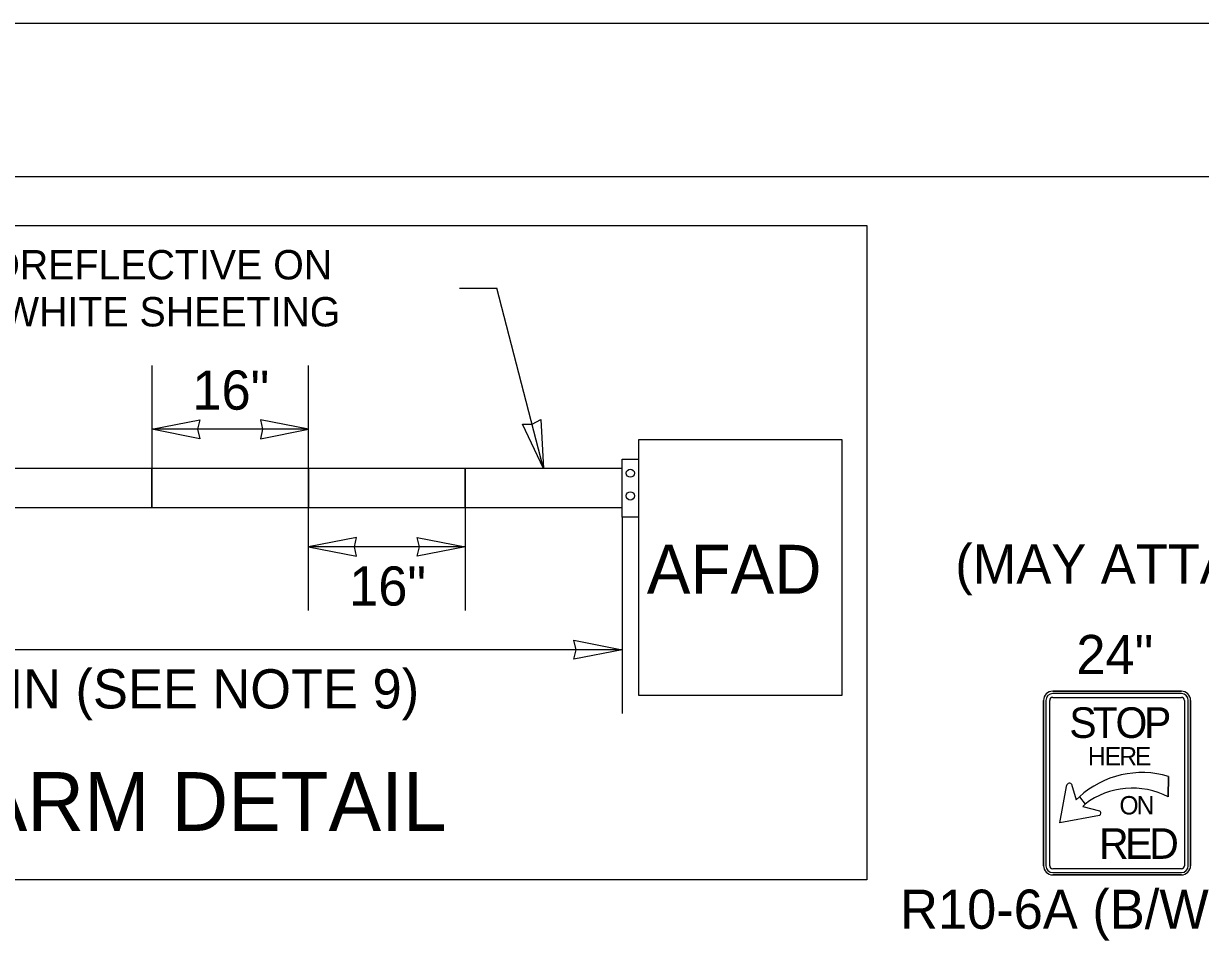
# Model space of a CAD drawing. Extents: x 99999.1 to 100095.7, y 99995 to 100010.7.
# Drawn here: x 100049.243 to 100051.645, y 100008.807 to 100010.687 of the extents above; entities that cross this region are included whole.
import ezdxf

# ---------------------------------------------------------------- set-up
doc = ezdxf.new("R2010")
doc.units = 0
for name, color, linetype in [('SH_GI_PlotLimits', 7, 'Continuous'), ('SH_GI_SheetBorder', 7, 'Continuous'), ('TR_SN_ConstructionSigns', 7, 'Continuous'), ('TR_WZ_WorkZoneDetails', 7, 'Continuous')]:
    doc.layers.add(name, color=color, linetype=linetype)

msp = doc.modelspace()

# ---------------------------------------------------------------- linework, layer by layer
at = {"layer": 'SH_GI_PlotLimits'}
msp.add_lwpolyline([(100039.0625, 99999.6875), (100056.0625, 99999.6875), (100056.0625, 100010.6875), (100039.0625, 100010.6875)], close=True, dxfattribs=at)
at = {"layer": 'SH_GI_SheetBorder'}
msp.add_line((100040, 100010.375), (100055.75, 100010.375), dxfattribs=at)
at = {"layer": 'TR_SN_ConstructionSigns'}
for p, q in [((100051.6061, 100009.3241), (100051.3436, 100009.3241)), ((100051.3436, 100009.3241), (100051.6061, 100009.3241)), ((100051.6061, 100009.3241), (100051.3436, 100009.3241)), ((100051.3436, 100009.3241), (100051.6061, 100009.3241)), ((100051.6061, 100009.3194), (100051.3436, 100009.3194)), ((100051.3436, 100009.3116), (100051.6061, 100009.3116)), ((100051.3249, 100009.3054), (100051.3249, 100008.9679)), ((100051.3249, 100008.9679), (100051.3249, 100009.3054)), ((100051.3249, 100009.3054), (100051.3249, 100008.9679)), ((100051.3249, 100008.9679), (100051.3249, 100009.3054)), ((100051.3296, 100009.3054), (100051.3296, 100008.9679)), ((100051.3374, 100008.9679), (100051.3374, 100009.3054)), ((100051.6124, 100009.3054), (100051.6124, 100008.9679)), ((100051.6202, 100008.9679), (100051.6202, 100009.3054)), ((100051.6249, 100008.9679), (100051.6249, 100009.3054)), ((100051.6249, 100009.3054), (100051.6249, 100008.9679)), ((100051.6249, 100008.9679), (100051.6249, 100009.3054)), ((100051.6249, 100009.3054), (100051.6249, 100008.9679)), ((100051.5798, 100009.1503), (100051.5795, 100009.1084)), ((100051.5795, 100009.1084), (100051.5798, 100009.1503)), ((100051.3577, 100009.0554), (100051.3713, 100009.1298)), ((100051.3821, 100009.1346), (100051.3915, 100009.1022)), ((100051.3915, 100009.1022), (100051.3979, 100009.1086)), ((100051.3979, 100009.1086), (100051.4095, 100009.0937)), ((100051.3979, 100009.1086), (100051.4095, 100009.0937)), ((100051.4095, 100009.0937), (100051.4048, 100009.0889)), ((100051.4048, 100009.0889), (100051.439, 100009.0797)), ((100051.4388, 100009.0704), (100051.3577, 100009.0554)), ((100051.6061, 100008.9616), (100051.3436, 100008.9616)), ((100051.3436, 100008.9538), (100051.6061, 100008.9538)), ((100051.3436, 100008.9491), (100051.6061, 100008.9491)), ((100051.6061, 100008.9491), (100051.3436, 100008.9491)), ((100051.3436, 100008.9491), (100051.6061, 100008.9491)), ((100051.6061, 100008.9491), (100051.3436, 100008.9491))]:
    msp.add_line(p, q, dxfattribs=at)
for centre, radius, start, end in [((100051.3436, 100009.3054), 0.0187, 90, 180), ((100051.3436, 100009.3054), 0.0187, 90, 180), ((100051.3436, 100009.3054), 0.0187, 90, 180), ((100051.3436, 100009.3054), 0.0187, 90, 180), ((100051.3436, 100009.3054), 0.0141, 90, 180), ((100051.3436, 100009.3054), 0.00625, 90, 180), ((100051.6061, 100009.3054), 0.0187, 0, 90), ((100051.6061, 100009.3054), 0.0187, 0, 90), ((100051.6061, 100009.3054), 0.0187, 0, 90), ((100051.6061, 100009.3054), 0.0187, 0, 90), ((100051.6061, 100009.3054), 0.0141, 0, 90), ((100051.6061, 100009.3054), 0.00625, 0, 90), ((100051.5261, 100008.9672), 0.1909, 73.6434, 132.2131), ((100051.5261, 100008.9672), 0.1909, 73.6434, 132.2131), ((100051.506, 100008.9678), 0.1586, 62.4149, 127.4769), ((100051.506, 100008.9678), 0.1586, 62.4149, 127.4769), ((100051.3436, 100008.9679), 0.0187, 180, 270), ((100051.3436, 100008.9679), 0.0187, 180, 270), ((100051.3436, 100008.9679), 0.0187, 180, 270), ((100051.3436, 100008.9679), 0.0187, 180, 270), ((100051.3436, 100008.9679), 0.0141, 180, 270), ((100051.3436, 100008.9679), 0.00625, 180, 270), ((100051.6061, 100008.9679), 0.0187, 270, 0), ((100051.6061, 100008.9679), 0.0187, 270, 0), ((100051.6061, 100008.9679), 0.0187, 270, 0), ((100051.6061, 100008.9679), 0.0141, 270, 0), ((100051.6061, 100008.9679), 0.00625, 270, 0), ((100051.6061, 100008.9679), 0.0187, 270, 0)]:
    msp.add_arc(centre, radius, start, end, dxfattribs=at)
for centre, major_axis, ratio, start_param, end_param in [((100051.3777, 100009.1299), (-0.00647, -0.00009), 0.989437, 3.962549, 6.283185), ((100051.4366, 100009.0751), (-0.0046, 0.00239), 0.999053, 2.490568, 4.712389)]:
    msp.add_ellipse(centre, major_axis=major_axis, ratio=ratio, start_param=start_param, end_param=end_param, dxfattribs=at)
at = {"layer": 'TR_WZ_WorkZoneDetails'}
for p, q in [((100050.1326, 100010.147), (100050.2088, 100010.147)), ((100050.3043, 100009.779), (100050.2088, 100010.147)), ((100049.5043, 100009.989), (100049.5043, 100009.779)), ((100049.8243, 100009.779), (100049.8243, 100009.989)), ((100049.8243, 100009.859), (100049.5043, 100009.859)), ((100049.8243, 100009.489), (100049.8243, 100009.699)), ((100050.1443, 100009.699), (100050.1443, 100009.489)), ((100050.4643, 100009.6797), (100050.4643, 100009.279)), ((100050.1443, 100009.619), (100049.8243, 100009.619)), ((100050.4643, 100009.409), (100048.6643, 100009.409))]:
    msp.add_line(p, q, dxfattribs=at)
for points in [[(100047.6374, 100010.275), (100050.9639, 100010.275), (100050.9639, 100008.939), (100047.6374, 100008.939)], [(100049.5043, 100009.859), (100049.6026, 100009.8783), (100049.5981, 100009.859), (100049.6026, 100009.8397)], [(100049.8243, 100009.859), (100049.7261, 100009.8783), (100049.7306, 100009.859), (100049.7261, 100009.8397)], [(100050.3043, 100009.779), (100050.2611, 100009.8693), (100050.2809, 100009.8697), (100050.2984, 100009.879)], [(100050.4643, 100009.7983), (100050.4977, 100009.7983), (100050.4977, 100009.6797), (100050.4643, 100009.6797)], [(100049.8243, 100009.619), (100049.9226, 100009.5997), (100049.9181, 100009.619), (100049.9226, 100009.6383)], [(100050.1443, 100009.619), (100050.0461, 100009.5997), (100050.0506, 100009.619), (100050.0461, 100009.6383)], [(100050.4643, 100009.409), (100050.3661, 100009.3897), (100050.3706, 100009.409), (100050.3661, 100009.4283)]]:
    msp.add_lwpolyline(points, close=True, dxfattribs=at)
for points in [[(100050.4977, 100009.6797), (100050.4977, 100009.3163), (100050.9139, 100009.3163), (100050.9139, 100009.8374), (100050.4977, 100009.8374), (100050.4977, 100009.7983), (100050.4977, 100009.6797)], [(100050.9139, 100009.8374), (100050.4977, 100009.8374), (100050.4977, 100009.3163), (100050.9139, 100009.3163), (100050.9139, 100009.8374)], [(100050.4643, 100009.779), (100048.6643, 100009.779), (100048.6643, 100009.699), (100050.4643, 100009.699), (100050.4643, 100009.779)], [(100049.1843, 100009.699), (100049.5043, 100009.699), (100049.5043, 100009.779), (100049.1843, 100009.779), (100049.1843, 100009.699)], [(100049.5043, 100009.699), (100049.8243, 100009.699), (100049.8243, 100009.779), (100049.5043, 100009.779), (100049.5043, 100009.699)], [(100049.8243, 100009.699), (100050.1443, 100009.699), (100050.1443, 100009.779), (100049.8243, 100009.779), (100049.8243, 100009.699)], [(100050.1443, 100009.699), (100050.4643, 100009.699), (100050.4643, 100009.779), (100050.1443, 100009.779), (100050.1443, 100009.699)]]:
    msp.add_lwpolyline(points, dxfattribs=at)
for centre, radius in [((100050.4813, 100009.7693), 0.00828), ((100050.4813, 100009.7229), 0.00855)]:
    msp.add_circle(centre, radius, dxfattribs=at)

# ---------------------------------------------------------------- texts
at = {"layer": 'TR_SN_ConstructionSigns'}
for s, p in [('(MAY ATTACH TO AFAD)', (100051.1446, 100009.5441)), ('24"', (100051.3918, 100009.3591)), ('R10-6A (B/W) or', (100051.032, 100008.8391))]:
    msp.add_text(s, height=0.08, rotation=360, dxfattribs=at).set_placement(p)
for s, height, p in [('S', 0.0625, (100051.3774, 100009.2288)), ('T', 0.0625, (100051.4249, 100009.2288)), ('O', 0.0625, (100051.4717, 100009.2288)), ('P', 0.0625, (100051.5299, 100009.2288)), ('H', 0.0375, (100051.4152, 100009.1726)), ('E', 0.0375, (100051.4497, 100009.1726)), ('R', 0.0375, (100051.4794, 100009.1726)), ('E', 0.0375, (100051.5112, 100009.1726)), ('O', 0.0375, (100051.4797, 100009.0726)), ('N', 0.0375, (100051.5146, 100009.0726)), ('R', 0.0625, (100051.4381, 100008.9819)), ('E', 0.0625, (100051.4913, 100008.9819)), ('D', 0.0625, (100051.5406, 100008.9819))]:
    msp.add_text(s, height=height, dxfattribs=at).set_placement(p)
at = {"layer": 'TR_WZ_WorkZoneDetails'}
for s, height, p in [('GATE ARM SHALL BE FULLY RETROREFLECTIVE ON', 0.06, (100047.8352, 100010.165)), ('BOTH SIDES WITH ALTERNATING RED/WHITE SHEETING', 0.06, (100047.6874, 100010.069)), ('16"', 0.08, (100049.5873, 100009.899)), ('AFAD', 0.1, (100050.5149, 100009.5231)), ('16"', 0.08, (100049.9073, 100009.499)), ('78" MIN (SEE NOTE 9)', 0.08, (100048.9363, 100009.289))]:
    msp.add_text(s, height=height, dxfattribs=at).set_placement(p)
msp.add_text('AFAD GATE ARM DETAIL', height=0.12, rotation=360, dxfattribs=at).set_placement((100048.1893, 100009.039))

doc.saveas('drawing.dxf')
